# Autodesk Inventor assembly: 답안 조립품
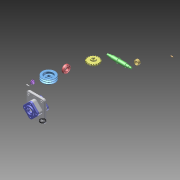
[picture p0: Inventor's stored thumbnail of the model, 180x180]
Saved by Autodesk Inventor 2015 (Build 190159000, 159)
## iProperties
Created: 2026-07
Part Number: 답안 조립품
Document SubType Name: Assembly
Designer: USER
Author: USER
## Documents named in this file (12)
- C:\Users\USER\Downloads\760705V1011\답안 조립품.iam
- C:\Users\USER\Downloads\760705V1011\본체.ipt
- C:\Users\USER\Downloads\760705V1011\가져온 구성요소\6각 구멍붙이 볼트 M6x16\6각 구멍붙이 볼트 M6x16.ipt
- C:\Users\USER\Downloads\760705V1011\가져온 구성요소\6각 플랜지 너트 M16\6각 플랜지 너트 M16.ipt
- C:\Users\USER\Downloads\760705V1011\가져온 구성요소\V-벨트풀리\V-벨트풀리.ipt
- C:\Users\USER\Downloads\760705V1011\가져온 구성요소\깊은 홈 볼 베어링 6206\깊은 홈 볼 베어링 6206.ipt
- C:\Users\USER\Downloads\760705V1011\가져온 구성요소\오일 실 30 45 8\오일 실 30 45 8.ipt
- C:\Users\USER\Downloads\760705V1011\가져온 구성요소\체인 스프로킷\체인 스프로킷.ipt
- C:\Users\USER\Downloads\760705V1011\가져온 구성요소\축\축.ipt
- C:\Users\USER\Downloads\760705V1011\가져온 구성요소\칼라\칼라.ipt
- C:\Users\USER\Downloads\760705V1011\가져온 구성요소\커버\커버.ipt
- C:\Users\USER\Downloads\760705V1011\가져온 구성요소\평행 키 6x6x20\평행 키 6x6x20.ipt
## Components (3 placed, 3 different names)
1. 6각 구멍붙이 볼트 M6x16:1
2. 6각 플랜지 너트 M16:1
3. V-벨트풀리:1
